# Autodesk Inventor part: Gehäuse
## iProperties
Created: 2007-03
Part Number: Gehäuse
Document SubType Name: Sheet Metal
Designer: Benno
Manufacturer: Standard
Standards Organization: Custom
Author: Benno
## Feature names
1. Bohrung1 [Hole]
2. Grobblech1
3. ExtrusionAbwicklung1
4. Ausschneiden1
